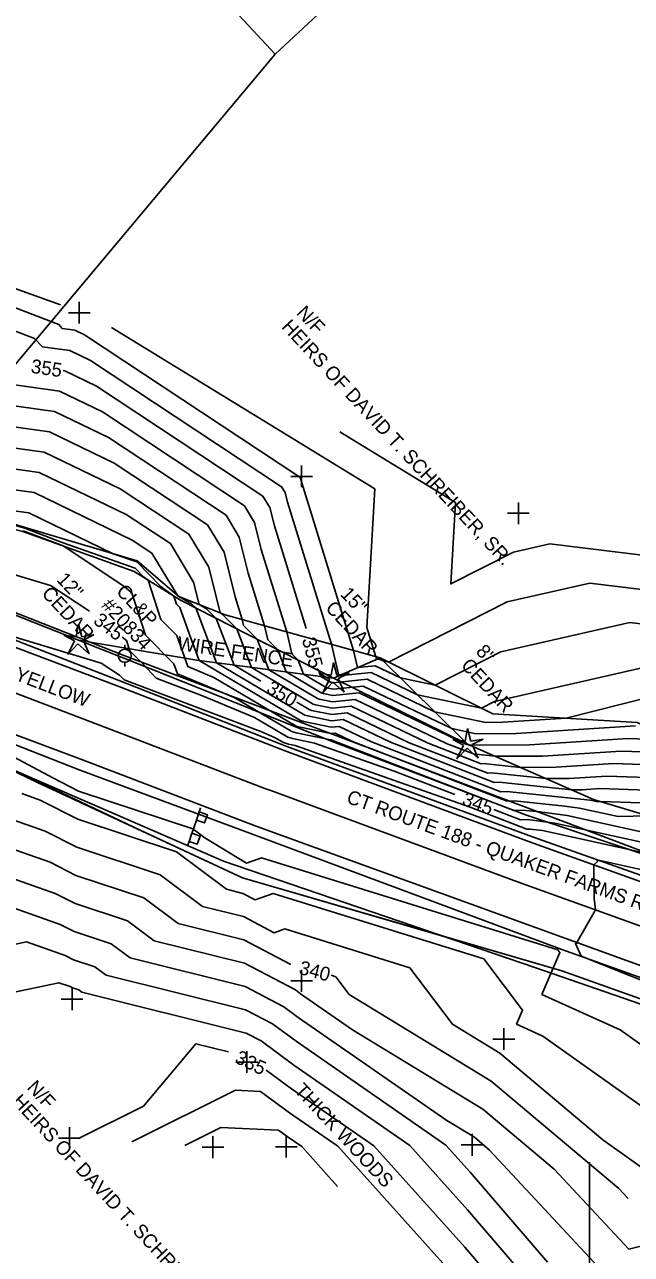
# Model space of a CAD drawing. Extents: x 487096 to 489566, y 221939 to 224454.
# Drawn here: x 487970.1 to 488109.6, y 223618.2 to 223900.8 of the extents above; entities that cross this region are included whole.
import ezdxf

# ---------------------------------------------------------------- set-up
doc = ezdxf.new("R2010")
doc.units = 0
for name, color, linetype in [('SV_BKLN_BKLN', 7, 'Continuous'), ('SV_BKLN_EARTH_TOP', 7, 'Continuous'), ('SV_CTRL_BM_INFO_BOX', 7, 'Continuous'), ('SV_FENC_FENCES', 7, 'Continuous'), ('SV_FENC_FENCES_TX', 7, 'Continuous'), ('SV_GRID_GRID', 7, 'Continuous'), ('SV_ROAD_BITRD', 7, 'Continuous'), ('SV_ROWL_HWYLOC', 7, 'Continuous'), ('SV_ROWL_ROWL_TX', 7, 'Continuous'), ('SV_SIGN_SIGN', 7, 'Continuous'), ('SV_SURF_INDEX_CONTOUR', 7, 'Continuous'), ('SV_SURF_INTER_CONTOUR', 7, 'Continuous'), ('SV_SURF_SPOT', 7, 'Continuous'), ('SV_TRAF_PVMTL', 7, 'Continuous'), ('SV_TRAF_TRAF_TX', 7, 'Continuous'), ('SV_TREE_TREELN', 7, 'Continuous'), ('SV_TREE_TREEVEG', 7, 'Continuous'), ('SV_TREE_TREEVEG_TX', 7, 'Continuous'), ('SV_UTOH_OVERHEAD_LINES', 7, 'Continuous'), ('SV_UTOH_UPO', 7, 'Continuous'), ('SV_UTOH_UTOH_TX', 7, 'Continuous'), ('SV_WALL_STONE_WALL', 7, 'Continuous')]:
    doc.layers.add(name, color=color, linetype=linetype)

msp = doc.modelspace()

# ---------------------------------------------------------------- linework, layer by layer
at = {"layer": 'SV_BKLN_BKLN'}
for points in [[(487885.7, 223821.61), (487905.24, 223822.04), (487927.4, 223802.77), (487938.91, 223792), (487969.73, 223784.31), (487995.3, 223775.15), (488005.95, 223768.55)], [(488005.95, 223768.55), (488041.14, 223750.63)]]:
    msp.add_lwpolyline(points, dxfattribs=at)
at = {"layer": 'SV_BKLN_EARTH_TOP'}
for points in [[(488041.14, 223750.63), (488051.84, 223755.29), (488071.96, 223735.45), (488100.92, 223722.74), (488124.66, 223715.6), (488155.68, 223709.25)], [(488156.25, 223662.12), (488127.21, 223671.39), (488093.65, 223683.37)]]:
    msp.add_lwpolyline(points, dxfattribs=at)
at = {"layer": 'SV_CTRL_BM_INFO_BOX'}
msp.add_line((488027.75, 223894.06), (487948.76, 223799.86), dxfattribs=at)
msp.add_lwpolyline([(487968.92, 224011.17), (488054.7, 223919.18), (488027.75, 223894.06), (487941.97, 223986.04)], close=True, dxfattribs=at)
at = {"layer": 'SV_FENC_FENCES'}
for points in [[(488168.14, 223658.69), (488156.25, 223662.12), (488127.21, 223671.39), (488093.65, 223683.37), (488020.23, 223704.76), (487973.09, 223726.63), (487930.05, 223747.42), (487880.61, 223763.01), (487833.81, 223784.33), (487750.08, 223817.31)], [(487982.51, 223759.36), (488009.69, 223754.74), (488041.14, 223750.63), (488071.96, 223735.45), (488100.92, 223722.74), (488124.66, 223715.6), (488155.68, 223709.25), (488178.9, 223706.07), (488184.09, 223703.51)]]:
    msp.add_lwpolyline(points, dxfattribs=at)
at = {"layer": 'SV_GRID_GRID'}
msp.add_line((488100, 223600), (488100, 223639.37), dxfattribs=at)
at = {"layer": 'SV_ROAD_BITRD'}
for points in [[(488195.32, 223676.23), (488156.88, 223689.32), (488086.86, 223714.16), (488030.43, 223734.89), (488029.27, 223735.37), (487991.62, 223750.14), (487935.77, 223771.81)], [(488093.67, 223688.29), (488022.87, 223714.61), (487982.7, 223729.58), (487929.37, 223750.5)], [(488178.96, 223657.88), (488093.67, 223688.29)]]:
    msp.add_lwpolyline(points, dxfattribs=at)
at = {"layer": 'SV_ROWL_HWYLOC'}
for points in [[(487756.92, 223854.03), (487819.74, 223823.93), (487982.51, 223759.36), (488009.69, 223754.74), (488041.14, 223750.63), (488071.96, 223735.45), (488100.92, 223722.74), (488124.66, 223715.6), (488155.68, 223709.25), (488178.9, 223706.07), (488296.16, 223658.56), (488379.4, 223617.17), (488410.15, 223595.68), (488443.8, 223549.21), (488472.24, 223469.86), (488477.06, 223418.16), (488475.62, 223352.08), (488474.08, 223317.48), (488463.17, 223231.25), (488461.58, 223189.46)], [(487750.08, 223817.31), (487833.81, 223784.33), (487880.61, 223763.01), (487930.05, 223747.42), (487951.57, 223737.03), (487996.66, 223715.69), (488020.23, 223704.76), (488056.94, 223694.06), (488093.65, 223683.37), (488127.21, 223671.39), (488156.25, 223662.12), (488168.14, 223658.69), (488264.6, 223621.9)]]:
    msp.add_lwpolyline(points, dxfattribs=at)
at = {"layer": 'SV_SIGN_SIGN'}
for p, q in [((488010.58, 223720.79), (488010.27, 223719.87)), ((488009.11, 223716.48), (488008.59, 223714.96)), ((488009.11, 223716.48), (488008.6, 223714.96)), ((488009.11, 223716.48), (488009.63, 223717.99)), ((488007.94, 223713.08), (488007.61, 223712.11))]:
    msp.add_line(p, q, dxfattribs=at)
for points in [[(488010.28, 223719.89), (488009.63, 223717.99), (488011.5, 223717.36), (488012.14, 223719.25)], [(488008.59, 223714.97), (488007.95, 223713.07), (488009.81, 223712.44), (488010.46, 223714.33)]]:
    msp.add_lwpolyline(points, close=True, dxfattribs=at)
at = {"layer": 'SV_SURF_INDEX_CONTOUR'}
for points in [[(487979.02, 223821.31), (487979.34, 223821.27), (487986.63, 223817.75), (488024.93, 223792.44), (488026.5, 223789.84), (488027.55, 223785.64), (488034.85, 223762.04)], [(487960.97, 223799.64), (487973.47, 223797.92), (487993.5, 223788.25), (488003.67, 223781.54), (488008.98, 223772.72), (488010.27, 223767.56), (488011.98, 223766.57), (488014.18, 223764.36), (488018.27, 223753.62), (488024.42, 223749.97)], [(487985.01, 223766), (487976.08, 223771.92), (487953.99, 223778.52), (487938.13, 223786.98), (487931.62, 223787.16), (487923.76, 223783.75), (487926.67, 223779.59), (487913.14, 223784.71)], [(488069.03, 223723.89), (488055.11, 223729.25), (488036.78, 223735.72), (488031.7, 223736.75), (488030.61, 223737.08), (488022.95, 223741.62), (488010.99, 223746.57), (488000.36, 223750.59), (487997.38, 223753.86), (487994.31, 223756.92), (487993.56, 223759.27), (487992.57, 223760.08)], [(488037.34, 223752.77), (488037.74, 223752.37), (488038.25, 223751.01), (488040.43, 223749.72), (488040.51, 223749.7), (488041.1, 223749.58), (488048.91, 223750.37), (488064.4, 223742.91), (488076.16, 223740.46), (488080.11, 223740.49), (488094.61, 223741.41), (488114.05, 223746.37), (488118.87, 223748.47)], [(488032.68, 223745.08), (488035.52, 223743.4), (488036.1, 223743.22), (488040.76, 223742.28), (488044.31, 223742.64), (488058.56, 223735.77), (488076.6, 223728.82), (488077.44, 223728.86), (488090.01, 223727.53), (488095.27, 223727.56), (488103.98, 223728.12), (488115.53, 223727.73)], [(488162.96, 223716.42), (488158.49, 223716.49), (488150.18, 223714.82), (488133.89, 223713.71), (488124.99, 223712.13), (488116.59, 223711.93), (488092.03, 223717.31), (488085.77, 223718.14), (488084.12, 223718.08), (488077.99, 223720.44)], [(487952.33, 223717.58), (487956.88, 223715.03), (487976.02, 223708.31), (487981.94, 223705.29), (487997.54, 223700.13), (488005.45, 223694.22), (488020.56, 223690.47), (488031.34, 223684.8)], [(488040.62, 223682.33), (488041.67, 223682.01), (488044.77, 223677.9), (488077.41, 223658.01), (488106.78, 223633.32), (488108.91, 223631.03)], [(487982.55, 223644.8), (487997.49, 223652.24), (488009.51, 223666.59), (488016.99, 223664.74)], [(488025.63, 223660.56), (488031.51, 223656.23), (488050.4, 223643.14), (488071.35, 223619.85), (488080.63, 223609.01), (488086.62, 223600.61)]]:
    msp.add_lwpolyline(points, dxfattribs=at)
at = {"layer": 'SV_SURF_INTER_CONTOUR'}
for points in [[(487978.37, 223836.41), (487918.82, 223857.78), (487893.24, 223860.08), (487887.4, 223862.23), (487879.08, 223862.67), (487846.53, 223867.61), (487802.76, 223890.71), (487802.25, 223889.59), (487792.04, 223888.75), (487787.06, 223888.11), (487782.82, 223891.17), (487767.31, 223917.05)], [(487924.69, 223852.33), (487977.96, 223831.88), (487978.79, 223831), (487981.69, 223830.6), (487983.88, 223829.55), (488033.44, 223796.8), (488033.51, 223796.69), (488033.55, 223796.51), (488045.78, 223756.98), (488046.69, 223753.05), (488050.75, 223753.46), (488056.51, 223750.69), (488064.5, 223749.03), (488079.62, 223756.68), (488109.3, 223763.45), (488120.18, 223762.12), (488136.47, 223761.14), (488153.26, 223760.68), (488156.87, 223762.06), (488164.73, 223764.89)], [(487925.08, 223846.87), (487972.43, 223828.69), (487974.22, 223826.8), (487980.52, 223825.94), (487985.26, 223823.65), (488029.19, 223794.62), (488030.01, 223793.27), (488030.55, 223791.08), (488040.65, 223758.4), (488042.35, 223751.16), (488049.83, 223751.92), (488060.45, 223746.8), (488075.2, 223743.73), (488078.17, 223745.23), (488114.8, 223753.59), (488118.21, 223754.46), (488118.37, 223754.53), (488118.61, 223754.47), (488149.76, 223753.62), (488156.61, 223756.24), (488165.17, 223759.32), (488168.79, 223760.94)], [(488157.93, 223768.17), (488157.13, 223767.88), (488156.77, 223767.74), (488155.06, 223767.79), (488122.09, 223769.78), (488100.08, 223772.47), (488081.07, 223768.13), (488053.8, 223754.32), (488052.56, 223754.58), (488051.67, 223755.01), (488051.04, 223754.94), (488050.9, 223755.55), (488048.82, 223762.28), (488050.68, 223794.13), (487990.14, 223831.22)], [(488110.56, 223739.65), (488083.14, 223737.9), (488073.97, 223737.85), (488068.34, 223739.02), (488047.99, 223748.82), (488041.03, 223748.12), (488039.63, 223748.4), (488039.45, 223748.46), (488034.26, 223751.53), (488033.02, 223754.77), (488031.58, 223756.22), (488030.41, 223761.24), (488024.55, 223780.21), (488023, 223786.42), (488020.68, 223790.26), (487988, 223811.85), (487978.17, 223816.6), (487965.1, 223818.39)], [(488113.07, 223736.63), (488108.92, 223736.77), (488086.17, 223735.32), (488072.45, 223735.24), (488072.11, 223735.27), (488072.09, 223735.27), (488071.6, 223735.46), (488047.07, 223747.28), (488040.96, 223746.66), (488038.75, 223747.11), (488038.47, 223747.19), (488030.26, 223752.05), (488028.31, 223757.16), (488026.04, 223759.46), (488025.29, 223762.67), (488021.55, 223774.77), (488019.49, 223783), (488016.43, 223788.08), (487989.38, 223805.95), (487976.99, 223811.93), (487960.54, 223814.18)], [(487955.98, 223809.98), (487975.82, 223807.26), (487990.75, 223800.05), (488012.17, 223785.9), (488015.99, 223779.57), (488018.54, 223769.34), (488020.17, 223764.09), (488020.49, 223762.7), (488023.6, 223759.56), (488026.26, 223752.57), (488037.49, 223745.93), (488037.86, 223745.81), (488040.89, 223745.2), (488046.15, 223745.73), (488067.25, 223735.57), (488073.59, 223733.12), (488073.89, 223733.13), (488078.3, 223732.67), (488089.2, 223732.73), (488107.27, 223733.88), (488114.72, 223733.63)], [(488134.49, 223776.81), (488124, 223777.44), (488090.86, 223781.48), (488082.52, 223779.58), (488068.09, 223772.27), (488069.18, 223790.99), (488042.62, 223807.26)], [(488116.37, 223730.64), (488105.63, 223731), (488092.24, 223730.15), (488084.16, 223730.1), (488075.66, 223730.99), (488075.09, 223730.97), (488062.91, 223735.67), (488045.23, 223744.18), (488040.83, 223743.74), (488036.98, 223744.52), (488036.5, 223744.67), (488022.27, 223753.1), (488018.89, 223761.96), (488015.44, 223765.44), (488015.11, 223765.63), (488012.49, 223776.15), (488007.92, 223783.72), (487992.13, 223794.15), (487974.64, 223802.59), (487951.42, 223805.78)], [(487942.29, 223797.37), (487972.29, 223793.26), (487994.88, 223782.35), (487999.41, 223779.36), (488005.21, 223769.74), (488005.46, 223769.49), (488005.61, 223769.38), (488008.53, 223767.7), (488009.47, 223766.76), (488014.27, 223754.14), (488034.54, 223742.14), (488035.22, 223741.93), (488040.69, 223740.82), (488043.39, 223741.09), (488054.22, 223735.88), (488078.1, 223726.67), (488079.22, 223726.72), (488095.87, 223724.96), (488098.3, 223724.98), (488102.34, 223725.23), (488119.67, 223724.65)], [(488121.32, 223721.66), (488102.42, 223722.29), (488101.6, 223722.27), (488100.53, 223722.51), (488100.13, 223722.56), (488081, 223724.58), (488079.61, 223724.53), (488049.87, 223735.98), (488042.47, 223739.55), (488040.63, 223739.36), (488034.34, 223740.63), (488033.55, 223740.87), (488010.28, 223754.66), (488008.33, 223759.78), (488005.78, 223766.9), (488005.04, 223767.64), (488004.45, 223769.48), (488001.48, 223771.71), (487995.91, 223777.33), (487990.5, 223779.23), (487971.12, 223788.59), (487949.48, 223791.55)], [(488113.41, 223718.98), (488106.6, 223718.83), (488097.7, 223720.78), (488094.34, 223721.22), (488082.78, 223722.44), (488081.11, 223722.38), (488045.53, 223736.08), (488041.55, 223738), (488040.56, 223737.9), (488033.46, 223739.34), (488032.57, 223739.61), (488013.66, 223750.81), (488007.67, 223753.29), (488005.12, 223760.43), (488001.47, 223764.07), (487998.54, 223773.14), (487997.49, 223773.93), (487995.51, 223775.92), (487978.77, 223781.81), (487970.17, 223785.07), (487955.08, 223789.29)], [(488111.6, 223715.38), (488094.86, 223719.04), (488088.55, 223719.88), (488084.55, 223720.3), (488082.62, 223720.23), (488041.18, 223736.19), (488040.63, 223736.45), (488040.49, 223736.44), (488032.58, 223738.05), (488031.59, 223738.35), (488018.31, 223746.21), (488005.29, 223751.61), (488004.46, 223753.95), (487997.89, 223760.49), (487994.76, 223770.21), (487992.68, 223771.92), (487978.99, 223781), (487969.82, 223784.47)], [(488218.77, 223725.98), (488178.17, 223713.79), (488175.6, 223713.43), (488172.46, 223713.1), (488157.27, 223713.35), (488152.57, 223712.41), (488143.34, 223711.77), (488125.33, 223708.57), (488121.59, 223708.49), (488089.19, 223715.58), (488086.37, 223715.95), (488085.63, 223715.93), (488072.54, 223720.97), (488032.36, 223735.14), (488030.82, 223735.46), (488029.62, 223735.82), (488027.6, 223737.02), (488024.43, 223738.33), (487992.98, 223750.21), (487991.95, 223751.33), (487987.72, 223754.08), (487959.79, 223762.49)], [(488123.88, 223657.84), (488107.05, 223669.79), (488089.06, 223677.96), (488093.19, 223687.54), (488092.71, 223688.18), (488024.6, 223709.32), (488021.12, 223708.09), (488011.53, 223713.93), (488008.77, 223715.99), (487982.54, 223724.66), (487976.59, 223727.71), (487967.61, 223732.53)], [(487969.52, 223724.08), (487973.73, 223722.6), (487982.34, 223718.2), (488005.03, 223710.7), (488016.52, 223702.12), (488020.31, 223701.17), (488023.13, 223699.69), (488027.26, 223701.16), (488075.69, 223686.12), (488084.62, 223674.31), (488083.23, 223671.11), (488089.25, 223668.38), (488120.94, 223645.88)], [(488118.01, 223633.91), (488103.1, 223644.49), (488079.35, 223664.46), (488068.5, 223671.07), (488058.68, 223684.06), (488029.92, 223692.99), (488027.47, 223692.12), (488020.44, 223695.82), (488010.99, 223698.17), (488001.28, 223705.42), (487982.14, 223711.75), (487974.88, 223715.46), (487963.2, 223719.55)], [(487955.64, 223708.72), (487977.16, 223701.17), (487981.74, 223698.83), (487993.8, 223694.84), (487999.91, 223690.27), (488020.69, 223685.11), (488032.39, 223678.96), (488033.54, 223678.11), (488045.48, 223669.84), (488075.48, 223651.56), (488091.91, 223637.75), (488109.01, 223619.39), (488125.07, 223623.34)], [(488132.77, 223701.96), (488101.76, 223708.87), (488101.86, 223708.49), (488100.97, 223707.73), (488101.1, 223699.95), (488101.36, 223697.38), (488097.08, 223689.89), (488096.99, 223689.6), (488096.75, 223689.64), (488098.07, 223686.73), (488154.11, 223664.37)], [(488104.23, 223612.98), (488077.03, 223642.18), (488073.54, 223645.11), (488067.18, 223648.98), (488033.03, 223672.64), (488029.76, 223675.05), (488020.81, 223679.76), (487994.37, 223686.32), (487990.06, 223689.55), (487981.54, 223692.37), (487978.3, 223694.02), (487963.1, 223699.35)], [(488090.31, 223616.38), (488072.57, 223637.08), (488066.97, 223643.31), (488032.53, 223667.17), (488027.13, 223671.15), (488020.94, 223674.4), (487988.84, 223682.38), (487986.31, 223684.26), (487981.33, 223685.91), (487979.44, 223686.88), (487970.56, 223689.99), (487947.14, 223685.07)], [(487944.71, 223673.63), (487978.02, 223680.63), (487980.58, 223679.73), (487981.13, 223679.45), (487982.57, 223678.97), (487983.3, 223678.43), (488021.07, 223669.05), (488024.5, 223667.24), (488032.02, 223661.7), (488058.69, 223643.22), (488071.96, 223628.46), (488090.93, 223606.33)], [(487994.77, 223644.03), (488018.65, 223655.92), (488024.36, 223655.66), (488031.01, 223650.75), (488042.12, 223643.06), (488069.64, 223612.46)], [(488042.09, 223633.8), (488033.84, 223642.97), (488030.5, 223645.28), (488028.51, 223646.75), (488015.25, 223647.37), (488006.98, 223643.25)]]:
    msp.add_lwpolyline(points, dxfattribs=at)
at = {"layer": 'SV_SURF_SPOT'}
for p, q in [((487982.7, 223832.11), (487982.7, 223837.11)), ((487980.2, 223834.61), (487985.2, 223834.61)), ((487982.7, 223834.61), (487982.7, 223834.61)), ((488033.82, 223794.5), (488033.82, 223799.5)), ((488031.32, 223797), (488036.32, 223797)), ((488033.82, 223797), (488033.82, 223797)), ((488083.65, 223786.03), (488083.65, 223791.03)), ((488081.15, 223788.53), (488086.15, 223788.53)), ((488083.65, 223788.53), (488083.65, 223788.53)), ((488033.81, 223678.56), (488033.81, 223683.56)), ((487981.05, 223674.32), (487981.05, 223679.32)), ((488031.31, 223681.06), (488036.31, 223681.06)), ((488033.81, 223681.06), (488033.81, 223681.06)), ((487978.55, 223676.82), (487983.55, 223676.82)), ((487981.05, 223676.82), (487981.05, 223676.82)), ((488080.31, 223665.17), (488080.31, 223670.17)), ((488077.81, 223667.67), (488082.81, 223667.67)), ((488080.31, 223667.67), (488080.31, 223667.67)), ((488018.72, 223662.39), (488023.72, 223662.39)), ((488021.22, 223659.89), (488021.22, 223664.89)), ((488021.22, 223662.39), (488021.22, 223662.39)), ((487980.41, 223642.44), (487980.41, 223647.44)), ((488030.29, 223640.44), (488030.29, 223645.44)), ((488073.02, 223640.87), (488073.02, 223645.87)), ((487977.91, 223644.94), (487982.91, 223644.94)), ((487980.41, 223644.94), (487980.41, 223644.94)), ((488010.94, 223642.84), (488015.95, 223642.84)), ((488013.44, 223640.34), (488013.44, 223645.34)), ((488013.44, 223642.84), (488013.44, 223642.84)), ((488027.79, 223642.94), (488032.79, 223642.94)), ((488030.29, 223642.94), (488030.29, 223642.94)), ((488070.52, 223643.37), (488075.52, 223643.37)), ((488073.02, 223643.37), (488073.02, 223643.37))]:
    msp.add_line(p, q, dxfattribs=at)
at = {"layer": 'SV_TRAF_PVMTL'}
for points in [[(488156.59, 223687.78), (488086.23, 223713.02), (488029.84, 223734), (488029.03, 223734.28), (487991.38, 223748.88), (487934.13, 223770.48)], [(488153.72, 223678.52), (488083.45, 223703.83), (488026.73, 223724.81), (488025.33, 223725.26), (487986.33, 223740.18), (487931.44, 223761.15)], [(488179.96, 223659.88), (488023.17, 223716.7), (487983.46, 223731.85), (487929.55, 223751.99)]]:
    msp.add_lwpolyline(points, dxfattribs=at)
at = {"layer": 'SV_TREE_TREELN'}
msp.add_lwpolyline([(487982.51, 223759.36), (488004.13, 223750.78), (488040.48, 223736.21), (488085.49, 223719.17), (488125.61, 223705.71), (488165.7, 223696.97), (488203.95, 223688.95)], dxfattribs=at)
at = {"layer": 'SV_TREE_TREEVEG'}
for p, q in [((487981.99, 223760.1), (487982.51, 223763.01)), ((487983.28, 223760.1), (487982.51, 223763.01)), ((487979.11, 223760.54), (487981.62, 223759.17)), ((487979.11, 223760.54), (487981.99, 223760.1)), ((487980.08, 223756.09), (487981.62, 223759.17)), ((487982.39, 223758.53), (487980.08, 223756.09)), ((487982.39, 223758.53), (487984.95, 223756.21)), ((487982.51, 223759.43), (487982.51, 223759.43)), ((487983.28, 223760.1), (487986.07, 223760.59)), ((487986.07, 223760.59), (487983.61, 223759.35)), ((487984.95, 223756.21), (487983.61, 223759.35)), ((488040.62, 223751.3), (488041.14, 223754.21)), ((488041.91, 223751.31), (488041.14, 223754.21)), ((488037.74, 223751.74), (488040.26, 223750.37)), ((488037.74, 223751.74), (488040.62, 223751.3)), ((488038.71, 223747.29), (488040.26, 223750.37)), ((488041.14, 223750.63), (488041.14, 223750.63)), ((488041.91, 223751.31), (488044.71, 223751.79)), ((488044.71, 223751.79), (488042.25, 223750.55)), ((488043.58, 223747.41), (488042.25, 223750.55)), ((488041.02, 223749.74), (488038.71, 223747.29)), ((488041.02, 223749.74), (488043.58, 223747.41)), ((488071.44, 223736.12), (488071.96, 223739.03)), ((488072.73, 223736.13), (488071.96, 223739.03)), ((488068.56, 223736.56), (488071.07, 223735.19)), ((488068.56, 223736.56), (488071.44, 223736.12)), ((488072.73, 223736.13), (488075.52, 223736.61)), ((488075.52, 223736.61), (488073.06, 223735.37)), ((488069.53, 223732.11), (488071.07, 223735.19)), ((488071.84, 223734.56), (488069.53, 223732.11)), ((488071.84, 223734.56), (488074.4, 223732.23)), ((488071.96, 223735.45), (488071.96, 223735.45)), ((488074.4, 223732.23), (488073.06, 223735.37))]:
    msp.add_line(p, q, dxfattribs=at)
msp.add_lwpolyline([(488167.81, 223598.31), (488191.14, 223648.28), (488087.41, 223684.16), (488015.83, 223708.57), (487929.95, 223745.8), (487829.66, 223784.61), (487827.21, 223771.15)], dxfattribs=at)
at = {"layer": 'SV_UTOH_OVERHEAD_LINES'}
msp.add_lwpolyline([(488477.01, 222631.44), (488424.13, 222778.25), (488391.68, 223012.96), (488449.87, 223205.72), (488470, 223438.33), (488349.56, 223622.89), (488159.18, 223693.12), (487993.17, 223755.78), (487804.2, 223830.22), (487742.26, 223860.21)], dxfattribs=at)
at = {"layer": 'SV_UTOH_UPO'}
for p, q in [((487993.15, 223757.26), (487993.15, 223758.26)), ((487993.17, 223753.29), (487993.17, 223754.28))]:
    msp.add_line(p, q, dxfattribs=at)
msp.add_circle((487993.15, 223755.78), 1.5, dxfattribs=at)
at = {"layer": 'SV_WALL_STONE_WALL'}
msp.add_lwpolyline([(487884.38, 223823.97), (487906, 223824.38), (487928.22, 223803.19), (487939.33, 223794.64), (487970.27, 223785.24), (487995.99, 223777.6), (488005.6, 223769.42), (488016.25, 223765.18), (488051.84, 223755.29), (488077.81, 223742.44), (488110.99, 223740.41), (488131.68, 223731.12)], dxfattribs=at)

# ---------------------------------------------------------------- texts
at = {"layer": 'SV_FENC_FENCES_TX'}
msp.add_text('WIRE FENCE', height=3.2, rotation=351.535, dxfattribs=at).set_placement((488005.11, 223757.14))
at = {"layer": 'SV_ROWL_ROWL_TX'}
for s, rotation, p in [('N/F', 313, (488032.44, 223834.42)), ('HEIRS OF DAVID T. SCHREIBER, SR.', 313, (488029.01, 223831.22)), ('CT ROUTE 188 - QUAKER FARMS ROAD', 339.923, (488043.92, 223722.06)), ('N/F', 313, (487970.48, 223656.39)), ('HEIRS OF DAVID T. SCHREIBER, SR.', 313, (487967.04, 223653.19))]:
    msp.add_text(s, height=3.2, rotation=rotation, dxfattribs=at).set_placement(p)
at = {"layer": 'SV_SURF_INDEX_CONTOUR'}
for s, rotation, p in [('355', 351.5175, (487971.42, 223820.83)), ('345', 321.9296, (487985.71, 223763.42)), ('355', 285.0217, (488033.86, 223759.55)), ('350', 329.3677, (488025.45, 223747.5)), ('345', 338.9313, (488070.46, 223721.62)), ('340', 345.1397, (488033.01, 223682.7)), ('335', 334.2034, (488018.23, 223662.38))]:
    msp.add_text(s, height=3.2, rotation=rotation, dxfattribs=at).set_placement(p)
at = {"layer": 'SV_TRAF_TRAF_TX'}
msp.add_text('DBL YELLOW', height=3.2, rotation=339.0964, dxfattribs=at).set_placement((487958.74, 223753.69))
at = {"layer": 'SV_TREE_TREEVEG_TX'}
for s, rotation, p in [('12"', 313.0386, (487977.3, 223773.12)), ('CEDAR', 313.0386, (487973.86, 223769.91)), ('15"', 313.0386, (488042.54, 223769.78)), ('CEDAR', 313.0386, (488039.1, 223766.57)), ('8"', 313.0386, (488073.69, 223756.58)), ('CEDAR', 313.0386, (488070.26, 223753.38)), ('THICK WOODS', 313, (488031.97, 223655.71))]:
    msp.add_text(s, height=3.2, rotation=rotation, dxfattribs=at).set_placement(p)
at = {"layer": 'SV_UTOH_UTOH_TX'}
for s, p in [('CL&P', (487991, 223770.4)), ('#20834', (487987.57, 223767.19))]:
    msp.add_text(s, height=3.2, rotation=313.0386, dxfattribs=at).set_placement(p)

doc.saveas('drawing.dxf')
